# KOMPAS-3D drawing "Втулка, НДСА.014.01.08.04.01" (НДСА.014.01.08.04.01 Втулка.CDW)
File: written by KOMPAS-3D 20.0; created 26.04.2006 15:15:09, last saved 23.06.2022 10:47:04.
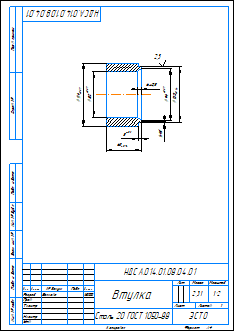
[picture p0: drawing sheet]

Sheet 1: A4, portrait

Document properties: Автор: Устинов А.В.; Организация: Эсто-вакуум; Полное имя файла: НДСА.014.01.08.04.01 Втулка.m3d; 246839097982: <item xmlns="http://appius.ru/pdm" xmlns:xs="http://www.w3.org/2001/XMLSchema" xmlns:xsi="http://www.w3.org/2001/XMLSchema-instance" xsi:type="item">  <element xmlns:d2p1="http://v8.1c.ru/8.1/data/enterprise/current-config" xsi:type="d2p1:CatalogRef.aps_Элемен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; PLM_CDWXDTO: <item xmlns="http://appius.ru/pdm" xmlns:xs="http://www.w3.org/2001/XMLSchema" xmlns:xsi="http://www.w3.org/2001/XMLSchema-instance" xsi:type="item">  <element xmlns:d2p1="http://v8.1c.ru/8.1/data/enterprise/current-config" xsi:type="d2p1:CatalogRef.aps_Элемен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; Масса: 2.30705

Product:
- Part/product: Втулка  | designation НДСА.014.01.08.04.01
    Материал: Сталь 20 ГОСТ 1050-88 (density 7859 kg/m3)
    Масса: 2.30705

Title block, sheet 1: Наименование: Втулка; designation: НДСА.014.01.08.04.01; Материал: Сталь 20 ГОСТ 1050-88; Масса: 2,31; scale: 1:2; Количество листов документа: 1; organisation: ЭСТО; Форматы листов документа: A4; stored path: D:\WorkPDM\Устинов А.В\8b0af0dc-f3da-4f92-ad11-61854faa3fd1\УКРД.789.01.03.10.01 Втулка.cdw; Разработал: Волкова; Разработал, date: 16.01.2020
Table, sheet 1:
  0^Material:V399CD8922A934364BF9D3DB1A16B3F75

Views: Вид 1, Сверху, Разрез А-А
Referenced files in E:\НДСА.014.01.08.00.00 Гидроподъемник\: НДСА.014.01.08.04.01 Втулка.m3d
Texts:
  НДСА.014.01.08.04.01 Втулка
Dimensions and other numbers on the sheet: 114; 100; 63; 82; 5; 1; 94; 6±0,5; 2,5; 1:2; 2,31; 16.01.2020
